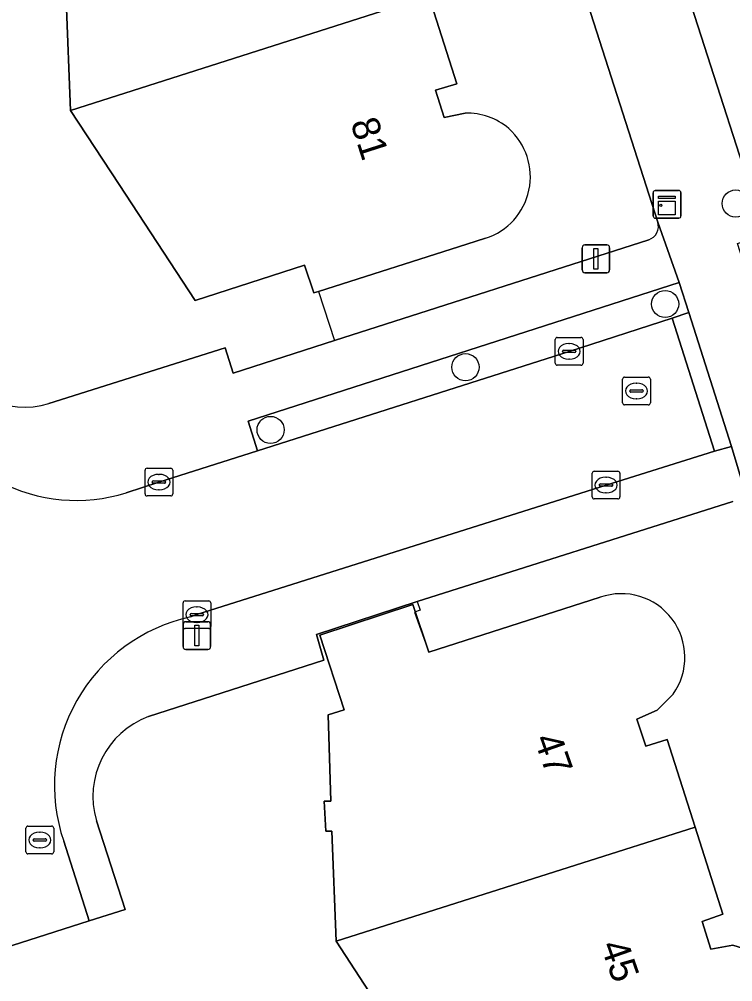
# Model space of a CAD drawing. Extents: x 159499 to 160349, y 382524 to 383273.
# Drawn here: x 159703.39 to 159729.11, y 382839.21 to 382873.89 of the extents above; entities that cross this region are included whole.
import ezdxf

# ---------------------------------------------------------------- set-up
doc = ezdxf.new("R2010")
doc.units = 0
for name, color, linetype in [('IMGEO_Boom', 7, 'Continuous'), ('IMGEO_Erf', 7, 'Continuous'), ('IMGEO_Groenvoorziening', 7, 'Continuous'), ('IMGEO_Kast', 7, 'Continuous'), ('IMGEO_Kolk', 7, 'Continuous'), ('IMGEO_Lichtmast', 7, 'Continuous'), ('IMGEO_Muur', 7, 'Continuous'), ('IMGEO_Pand', 7, 'Continuous'), ('IMGEO_Pand_nummerreeks', 7, 'Continuous'), ('IMGEO_Rijbaan_lokaal_open', 7, 'Continuous'), ('IMGEO_Rioolput', 7, 'Continuous'), ('IMGEO_Voetpad_open', 7, 'Continuous')]:
    doc.layers.add(name, color=color, linetype=linetype)

msp = doc.modelspace()

# ---------------------------------------------------------------- linework, layer by layer
at = {"layer": 'IMGEO_Boom'}
for centre in [(159729.218, 382867.25), (159726.676, 382863.629), (159719.477, 382861.354), (159712.452, 382859.093)]:
    msp.add_circle(centre, 0.489, dxfattribs=at)
at = {"layer": 'IMGEO_Erf'}
for points in [[(159726.407, 382866.582), (159705.82, 382930.705)], [(159716.052, 382878.641), (159716.38, 382877.657), (159717.146, 382877.885), (159718.157, 382874.729), (159719.171, 382871.564), (159718.394, 382871.332), (159718.71, 382870.347), (159719.467, 382870.509)], [(159720.203, 382865.998), (159719.528, 382865.788), (159714.185, 382864.083), (159714.015, 382864.029), (159713.674, 382865.027), (159709.737, 382863.757), (159706.992, 382867.936), (159705.241, 382870.601), (159704.925, 382878.587)], [(159704.459, 382860.04), (159710.809, 382862.055), (159711.101, 382861.14), (159714.761, 382862.313), (159726.084, 382865.943)], [(159706.174, 382845.013), (159707.207, 382841.819), (159705.912, 382841.405), (159664.868, 382828.266), (159663.864, 382831.383), (159666.542, 382832.265), (159661.739, 382847.267), (159659.033, 382846.414), (159658.047, 382849.524), (159699.119, 382862.705), (159700.405, 382863.118), (159700.812, 382861.848)], [(159729.113, 382856.514), (159717.74, 382852.909), (159714.109, 382851.726), (159714.375, 382850.795), (159708.057, 382848.765)], [(159714.223, 382851.698), (159717.585, 382852.806), (159718.151, 382851.09), (159724.337, 382853.063)], [(159734.475, 382821.398), (159728.286, 382819.442), (159728.827, 382818.014), (159725.74, 382817.391), (159725.188, 382819.543), (159724.024, 382819.172), (159719.547, 382825.96), (159719.219, 382833.928), (159714.816, 382840.671), (159714.658, 382844.641), (159714.438, 382844.631), (159714.386, 382845.722), (159714.626, 382845.723), (159714.532, 382848.826), (159715.109, 382849.012), (159714.223, 382851.698)], [(159726.963, 382849.575), (159726.392, 382848.995), (159725.65, 382848.673), (159725.979, 382847.696), (159726.751, 382847.942), (159727.759, 382844.784), (159728.761, 382841.646), (159728.006, 382841.381), (159728.326, 382840.39), (159729.119, 382840.528), (159729.847, 382840.303)]]:
    msp.add_lwpolyline(points, dxfattribs=at)
for centre, radius, start, end in [((159719.534, 382868.211), 2.299, 49.1866, 91.6585), ((159719.491, 382868.212), 2.326, 287.8266, 48.3742), ((159725.926, 382866.424), 0.506, 288.1944, 18.1745), ((159703.607, 382862.904), 2.988, 200.6996, 286.5606), ((159725.097, 382850.903), 2.29, 324.5583, 109.3915), ((159709.121, 382845.882), 3.073, 110.2611, 196.4379)]:
    msp.add_arc(centre, radius, start, end, dxfattribs=at)
at = {"layer": 'IMGEO_Groenvoorziening'}
msp.add_lwpolyline([(159711.979, 382858.343), (159723.216, 382861.922), (159726.932, 382863.118), (159727.53, 382863.325), (159727.182, 382864.402), (159711.648, 382859.405)], close=True, dxfattribs=at)
at = {"layer": 'IMGEO_Kast'}
for p, q in [((159726.243, 382866.796), (159726.243, 382867.637)), ((159726.243, 382867.637), (159726.243, 382866.796)), ((159726.318, 382867.721), (159727.159, 382867.721)), ((159727.159, 382867.721), (159726.318, 382867.721)), ((159727.243, 382867.646), (159727.243, 382866.805)), ((159727.243, 382866.805), (159727.243, 382867.646)), ((159727.168, 382866.721), (159726.327, 382866.721)), ((159726.327, 382866.721), (159727.168, 382866.721))]:
    msp.add_line(p, q, dxfattribs=at)
for points in [[(159726.438, 382867.511), (159727.038, 382867.511), (159727.038, 382867.426), (159726.438, 382867.426), (159726.438, 382867.511)], [(159726.438, 382867.336), (159727.038, 382867.336), (159727.038, 382866.847), (159726.438, 382866.847), (159726.438, 382867.336)]]:
    msp.add_lwpolyline(points, dxfattribs=at)
msp.add_circle((159726.522, 382867.185), 0.0377, dxfattribs=at)
for centre, start, end in [((159726.321, 382867.643), 92.4484, 184.2845), ((159726.321, 382867.643), 92.4484, 184.2845), ((159727.165, 382867.643), 2.4484, 94.2845), ((159727.165, 382867.643), 2.4484, 94.2845), ((159727.165, 382866.799), 272.4484, 4.2845), ((159727.165, 382866.799), 272.4484, 4.2845), ((159726.321, 382866.799), 182.4484, 274.2845), ((159726.321, 382866.799), 182.4484, 274.2845)]:
    msp.add_arc(centre, 0.0779, start, end, dxfattribs=at)
at = {"layer": 'IMGEO_Kolk'}
for p, q in [((159722.714, 382861.497), (159722.714, 382862.349)), ((159722.789, 382862.423), (159723.641, 382862.423)), ((159723.715, 382862.349), (159723.715, 382861.497)), ((159723.016, 382861.966), (159723.414, 382861.966)), ((159723.202, 382862.203), (159723.227, 382862.203)), ((159722.973, 382861.917), (159722.973, 382861.929)), ((159723.411, 382861.88), (159723.013, 382861.88)), ((159723.225, 382861.643), (159723.2, 382861.643)), ((159723.457, 382861.929), (159723.457, 382861.917)), ((159723.641, 382861.423), (159722.789, 382861.423)), ((159707.926, 382856.787), (159707.926, 382857.639)), ((159708.001, 382857.713), (159708.853, 382857.713)), ((159708.414, 382857.493), (159708.439, 382857.493)), ((159708.927, 382857.639), (159708.927, 382856.787)), ((159724.044, 382856.68), (159724.044, 382857.532)), ((159724.119, 382857.606), (159724.971, 382857.606)), ((159725.045, 382857.532), (159725.045, 382856.68)), ((159708.185, 382857.207), (159708.185, 382857.219)), ((159708.623, 382857.17), (159708.225, 382857.17)), ((159708.228, 382857.256), (159708.626, 382857.256)), ((159708.669, 382857.219), (159708.669, 382857.207)), ((159724.303, 382857.1), (159724.303, 382857.112)), ((159724.346, 382857.149), (159724.744, 382857.149)), ((159724.532, 382857.386), (159724.557, 382857.386)), ((159724.787, 382857.112), (159724.787, 382857.1)), ((159708.437, 382856.933), (159708.412, 382856.933)), ((159724.741, 382857.063), (159724.343, 382857.063)), ((159724.555, 382856.826), (159724.53, 382856.826)), ((159708.853, 382856.713), (159708.001, 382856.713)), ((159724.971, 382856.606), (159724.119, 382856.606)), ((159709.37, 382852.935), (159710.222, 382852.935)), ((159709.295, 382852.009), (159709.295, 382852.861)), ((159709.783, 382852.715), (159709.808, 382852.715)), ((159710.296, 382852.861), (159710.296, 382852.009)), ((159709.554, 382852.429), (159709.554, 382852.441)), ((159709.992, 382852.392), (159709.594, 382852.392)), ((159709.597, 382852.478), (159709.995, 382852.478)), ((159710.038, 382852.441), (159710.038, 382852.429)), ((159710.222, 382851.935), (159709.37, 382851.935)), ((159709.806, 382852.155), (159709.781, 382852.155))]:
    msp.add_line(p, q, dxfattribs=at)
for points in [[(159722.714, 382861.497), (159722.714, 382862.349)], [(159722.789, 382862.423), (159723.641, 382862.423)], [(159723.715, 382862.349), (159723.715, 382861.497)], [(159723.641, 382861.423), (159722.789, 382861.423)], [(159707.926, 382856.787), (159707.926, 382857.639)], [(159708.001, 382857.713), (159708.853, 382857.713)], [(159708.927, 382857.639), (159708.927, 382856.787)], [(159724.044, 382856.68), (159724.044, 382857.532)], [(159724.119, 382857.606), (159724.971, 382857.606)], [(159725.045, 382857.532), (159725.045, 382856.68)], [(159708.853, 382856.713), (159708.001, 382856.713)], [(159724.971, 382856.606), (159724.119, 382856.606)], [(159709.37, 382852.935), (159710.222, 382852.935)], [(159709.295, 382852.009), (159709.295, 382852.861)], [(159710.296, 382852.861), (159710.296, 382852.009)], [(159710.222, 382851.935), (159709.37, 382851.935)]]:
    msp.add_lwpolyline(points, dxfattribs=at)
for centre, radius, start, end in [((159722.791, 382862.347), 0.0765, 91.552, 178.448), ((159722.791, 382862.347), 0.0765, 91.552, 178.448), ((159723.639, 382862.347), 0.0765, 1.552, 88.448), ((159723.639, 382862.347), 0.0765, 1.552, 88.448), ((159723.013, 382861.926), 0.0403, 85.8775, 175.7526), ((159723.418, 382861.928), 0.0386, 1.7309, 96.639), ((159723.01, 382861.916), 0.0366, 178.938, 274.7102), ((159723.414, 382861.923), 0.043, 264.8664, 352.4533), ((159722.791, 382861.499), 0.0765, 181.552, 268.448), ((159722.791, 382861.499), 0.0765, 181.552, 268.448), ((159723.639, 382861.499), 0.0765, 271.552, 358.448), ((159723.639, 382861.499), 0.0765, 271.552, 358.448), ((159708.003, 382857.637), 0.0765, 91.552, 178.448), ((159708.003, 382857.637), 0.0765, 91.552, 178.448), ((159708.851, 382857.637), 0.0765, 1.552, 88.448), ((159708.851, 382857.637), 0.0765, 1.552, 88.448), ((159724.121, 382857.53), 0.0765, 91.552, 178.448), ((159724.121, 382857.53), 0.0765, 91.552, 178.448), ((159724.969, 382857.53), 0.0765, 1.552, 88.448), ((159724.969, 382857.53), 0.0765, 1.552, 88.448), ((159708.225, 382857.216), 0.0403, 85.8775, 175.7526), ((159708.222, 382857.206), 0.0366, 178.938, 274.7102), ((159708.626, 382857.213), 0.043, 264.8664, 352.4533), ((159708.63, 382857.218), 0.0386, 1.7309, 96.639), ((159724.343, 382857.109), 0.0403, 85.8775, 175.7526), ((159724.34, 382857.099), 0.0366, 178.938, 274.7102), ((159724.744, 382857.106), 0.043, 264.8664, 352.4533), ((159724.748, 382857.111), 0.0386, 1.7309, 96.639), ((159708.003, 382856.789), 0.0765, 181.552, 268.448), ((159708.003, 382856.789), 0.0765, 181.552, 268.448), ((159708.851, 382856.789), 0.0765, 271.552, 358.448), ((159708.851, 382856.789), 0.0765, 271.552, 358.448), ((159724.121, 382856.682), 0.0765, 181.552, 268.448), ((159724.121, 382856.682), 0.0765, 181.552, 268.448), ((159724.969, 382856.682), 0.0765, 271.552, 358.448), ((159724.969, 382856.682), 0.0765, 271.552, 358.448), ((159709.372, 382852.859), 0.0765, 91.552, 178.448), ((159709.372, 382852.859), 0.0765, 91.552, 178.448), ((159710.22, 382852.859), 0.0765, 1.552, 88.448), ((159710.22, 382852.859), 0.0765, 1.552, 88.448), ((159709.594, 382852.438), 0.0403, 85.8775, 175.7526), ((159709.591, 382852.428), 0.0366, 178.938, 274.7102), ((159709.995, 382852.435), 0.043, 264.8664, 352.4533), ((159709.999, 382852.44), 0.0386, 1.7309, 96.639), ((159709.372, 382852.011), 0.0765, 181.552, 268.448), ((159709.372, 382852.011), 0.0765, 181.552, 268.448), ((159710.22, 382852.011), 0.0765, 271.552, 358.448), ((159710.22, 382852.011), 0.0765, 271.552, 358.448)]:
    msp.add_arc(centre, radius, start, end, dxfattribs=at)
for centre, major_axis, ratio, start_param, end_param in [((159723.201, 382861.923), (-0.387, 0.002), 0.722429, 4.712389, 7.853982), ((159723.226, 382861.923), (-0.39, 0.002), 0.717154, 1.570796, 4.712389), ((159708.413, 382857.213), (-0.387, 0.002), 0.722429, 4.712389, 7.853982), ((159708.438, 382857.213), (-0.39, 0.002), 0.717154, 1.570796, 4.712389), ((159724.531, 382857.106), (-0.387, 0.002), 0.722429, 4.712389, 7.853982), ((159724.556, 382857.106), (-0.39, 0.002), 0.717154, 1.570796, 4.712389), ((159709.782, 382852.435), (-0.387, 0.002), 0.722429, 4.712389, 7.853982), ((159709.807, 382852.435), (-0.39, 0.002), 0.717154, 1.570796, 4.712389)]:
    msp.add_ellipse(centre, major_axis=major_axis, ratio=ratio, start_param=start_param, end_param=end_param, dxfattribs=at)
at = {"layer": 'IMGEO_Lichtmast'}
for p, q in [((159723.684, 382864.859), (159723.684, 382865.659)), ((159723.684, 382865.659), (159723.684, 382864.859)), ((159723.784, 382865.759), (159724.574, 382865.759)), ((159724.574, 382865.759), (159723.784, 382865.759)), ((159724.674, 382865.659), (159724.674, 382864.859)), ((159724.674, 382864.859), (159724.674, 382865.659)), ((159724.574, 382864.759), (159723.784, 382864.759)), ((159723.784, 382864.759), (159724.574, 382864.759)), ((159709.298, 382851.284), (159709.298, 382852.084)), ((159709.298, 382852.084), (159709.298, 382851.284)), ((159709.398, 382852.184), (159710.188, 382852.184)), ((159710.188, 382852.184), (159709.398, 382852.184)), ((159710.288, 382852.084), (159710.288, 382851.284)), ((159710.288, 382851.284), (159710.288, 382852.084)), ((159710.188, 382851.184), (159709.398, 382851.184)), ((159709.398, 382851.184), (159710.188, 382851.184))]:
    msp.add_line(p, q, dxfattribs=at)
for points in [[(159724.104, 382865.634), (159724.254, 382865.634), (159724.254, 382864.884), (159724.104, 382864.884), (159724.104, 382865.634)], [(159709.718, 382852.059), (159709.868, 382852.059), (159709.868, 382851.309), (159709.718, 382851.309), (159709.718, 382852.059)]]:
    msp.add_lwpolyline(points, dxfattribs=at)
for centre, start, end in [((159723.784, 382865.659), 90, 180), ((159723.784, 382865.659), 90, 180), ((159724.574, 382865.659), 0, 90), ((159724.574, 382865.659), 360, 90), ((159723.784, 382864.859), 180, 270), ((159723.784, 382864.859), 180, 270), ((159724.574, 382864.859), 270, 0), ((159724.574, 382864.859), 270, 0), ((159709.398, 382852.084), 90, 180), ((159709.398, 382852.084), 90, 180), ((159710.188, 382852.084), 0, 90), ((159710.188, 382852.084), 360, 90), ((159709.398, 382851.284), 180, 270), ((159709.398, 382851.284), 180, 270), ((159710.188, 382851.284), 270, 0), ((159710.188, 382851.284), 270, 0)]:
    msp.add_arc(centre, 0.1, start, end, dxfattribs=at)
at = {"layer": 'IMGEO_Muur'}
for points in [[(159714.185, 382864.083), (159714.761, 382862.313)], [(159714.761, 382862.313), (159711.101, 382861.14), (159710.809, 382862.055), (159704.459, 382860.04)], [(159708.057, 382848.765), (159714.375, 382850.795), (159714.109, 382851.726), (159717.74, 382852.909)], [(159717.74, 382852.909), (159717.841, 382852.604), (159717.635, 382852.523), (159718.151, 382851.09)], [(159706.174, 382845.013), (159707.207, 382841.819)]]:
    msp.add_lwpolyline(points, dxfattribs=at)
for centre, radius, start, end in [((159703.607, 382862.904), 2.988, 200.6996, 286.5606), ((159709.121, 382845.882), 3.073, 110.2611, 196.4379)]:
    msp.add_arc(centre, radius, start, end, dxfattribs=at)
at = {"layer": 'IMGEO_Pand'}
for points in [[(159717.354, 382882.542), (159704.925, 382878.587), (159705.241, 382870.601), (159718.157, 382874.729), (159717.146, 382877.885), (159716.38, 382877.657), (159716.052, 382878.641)], [(159719.467, 382870.509), (159718.71, 382870.347), (159718.394, 382871.332), (159719.171, 382871.564), (159718.157, 382874.729), (159705.241, 382870.601), (159706.992, 382867.936), (159709.737, 382863.757), (159713.674, 382865.027), (159714.015, 382864.029), (159714.185, 382864.083), (159719.528, 382865.788), (159720.203, 382865.998)], [(159724.337, 382853.063), (159718.151, 382851.09), (159717.585, 382852.806), (159714.223, 382851.698), (159715.109, 382849.012), (159714.532, 382848.826), (159714.626, 382845.723), (159714.386, 382845.722), (159714.438, 382844.631), (159714.658, 382844.641), (159714.816, 382840.671), (159727.759, 382844.784), (159726.751, 382847.942)], [(159726.751, 382847.942), (159725.979, 382847.696), (159725.65, 382848.673), (159726.392, 382848.995), (159726.963, 382849.575)], [(159729.847, 382840.303), (159729.119, 382840.528), (159728.326, 382840.39), (159728.006, 382841.381), (159728.761, 382841.646), (159727.759, 382844.784), (159714.816, 382840.671), (159719.219, 382833.928), (159731.651, 382837.94)]]:
    msp.add_lwpolyline(points, dxfattribs=at)
for centre, radius, start, end in [((159719.534, 382868.211), 2.299, 49.1866, 91.6585), ((159719.491, 382868.212), 2.326, 287.8266, 48.3742), ((159725.097, 382850.903), 2.29, 324.5583, 109.3915)]:
    msp.add_arc(centre, radius, start, end, dxfattribs=at)
at = {"layer": 'IMGEO_Rijbaan_lokaal_open'}
msp.add_lwpolyline([(159737.432, 382843.824), (159744.243, 382846.026), (159744.191, 382846.188), (159737.539, 382866.925), (159727.07, 382899.511), (159726.994, 382899.746), (159720.253, 382897.428), (159720.284, 382897.331), (159721.097, 382894.788), (159722.888, 382889.098), (159725.791, 382880.115), (159727.623, 382874.357), (159730.279, 382866.12), (159733.33, 382856.538), (159733.407, 382856.312), (159735.46, 382849.969), (159737.305, 382844.219)], close=True, dxfattribs=at)
for points in [[(159709.567, 382852.354), (159709.795, 382852.437), (159724.544, 382857.107), (159728.46, 382858.329), (159726.932, 382863.118), (159723.216, 382861.922), (159711.979, 382858.343), (159708.428, 382857.212), (159707.25, 382856.83)], [(159699.712, 382860.799), (159699.119, 382862.705), (159658.047, 382849.524), (159659.033, 382846.414), (159661.739, 382847.267), (159666.542, 382832.265), (159663.864, 382831.383), (159664.868, 382828.266), (159705.912, 382841.405), (159704.996, 382844.273)]]:
    msp.add_lwpolyline(points, dxfattribs=at)
for centre, radius, start, end in [((159705.451, 382862.556), 6.002, 197.02, 287.4435), ((159710.87, 382846.283), 6.209, 102.1186, 198.8922)]:
    msp.add_arc(centre, radius, start, end, dxfattribs=at)
at = {"layer": 'IMGEO_Rioolput'}
for p, q in [((159725.141, 382860.069), (159725.141, 382860.921)), ((159725.216, 382860.995), (159726.068, 382860.995)), ((159726.142, 382860.921), (159726.142, 382860.069)), ((159725.629, 382860.775), (159725.654, 382860.775)), ((159725.4, 382860.489), (159725.4, 382860.501)), ((159725.838, 382860.452), (159725.44, 382860.452)), ((159725.443, 382860.538), (159725.841, 382860.538)), ((159725.652, 382860.215), (159725.627, 382860.215)), ((159725.884, 382860.501), (159725.884, 382860.489)), ((159726.068, 382859.995), (159725.216, 382859.995)), ((159703.632, 382843.892), (159703.632, 382844.744)), ((159703.707, 382844.818), (159704.559, 382844.818)), ((159704.633, 382844.744), (159704.633, 382843.892)), ((159703.891, 382844.312), (159703.891, 382844.324)), ((159704.329, 382844.275), (159703.931, 382844.275)), ((159703.934, 382844.361), (159704.332, 382844.361)), ((159704.12, 382844.598), (159704.145, 382844.598)), ((159704.375, 382844.324), (159704.375, 382844.312)), ((159704.143, 382844.038), (159704.118, 382844.038)), ((159704.559, 382843.818), (159703.707, 382843.818))]:
    msp.add_line(p, q, dxfattribs=at)
for points in [[(159725.141, 382860.069), (159725.141, 382860.921)], [(159725.216, 382860.995), (159726.068, 382860.995)], [(159726.142, 382860.921), (159726.142, 382860.069)], [(159726.068, 382859.995), (159725.216, 382859.995)], [(159703.632, 382843.892), (159703.632, 382844.744)], [(159703.707, 382844.818), (159704.559, 382844.818)], [(159704.633, 382844.744), (159704.633, 382843.892)], [(159704.559, 382843.818), (159703.707, 382843.818)]]:
    msp.add_lwpolyline(points, dxfattribs=at)
for centre, radius, start, end in [((159725.218, 382860.919), 0.0765, 91.552, 178.448), ((159725.218, 382860.919), 0.0765, 91.552, 178.448), ((159726.066, 382860.919), 0.0765, 1.552, 88.448), ((159726.066, 382860.919), 0.0765, 1.552, 88.448), ((159725.44, 382860.498), 0.0403, 85.8775, 175.7526), ((159725.437, 382860.488), 0.0366, 178.938, 274.7102), ((159725.841, 382860.495), 0.043, 264.8664, 352.4533), ((159725.845, 382860.5), 0.0386, 1.7309, 96.639), ((159725.218, 382860.071), 0.0765, 181.552, 268.448), ((159725.218, 382860.071), 0.0765, 181.552, 268.448), ((159726.066, 382860.071), 0.0765, 271.552, 358.448), ((159726.066, 382860.071), 0.0765, 271.552, 358.448), ((159703.709, 382844.742), 0.0765, 91.552, 178.448), ((159703.709, 382844.742), 0.0765, 91.552, 178.448), ((159704.557, 382844.742), 0.0765, 1.552, 88.448), ((159704.557, 382844.742), 0.0765, 1.552, 88.448), ((159703.931, 382844.321), 0.0403, 85.8775, 175.7526), ((159703.928, 382844.311), 0.0366, 178.938, 274.7102), ((159704.332, 382844.318), 0.043, 264.8664, 352.4533), ((159704.336, 382844.323), 0.0386, 1.7309, 96.639), ((159703.709, 382843.894), 0.0765, 181.552, 268.448), ((159703.709, 382843.894), 0.0765, 181.552, 268.448), ((159704.557, 382843.894), 0.0765, 271.552, 358.448), ((159704.557, 382843.894), 0.0765, 271.552, 358.448)]:
    msp.add_arc(centre, radius, start, end, dxfattribs=at)
for centre, major_axis, ratio, start_param, end_param in [((159725.628, 382860.495), (-0.387, 0.002), 0.722429, 4.712389, 7.853982), ((159725.653, 382860.495), (-0.39, 0.002), 0.717154, 1.570796, 4.712389), ((159704.119, 382844.318), (-0.387, 0.002), 0.722429, 4.712389, 7.853982), ((159704.144, 382844.318), (-0.39, 0.002), 0.717154, 1.570796, 4.712389)]:
    msp.add_ellipse(centre, major_axis=major_axis, ratio=ratio, start_param=start_param, end_param=end_param, dxfattribs=at)
at = {"layer": 'IMGEO_Voetpad_open'}
for points in [[(159705.82, 382930.705), (159726.407, 382866.582), (159727.182, 382864.402), (159727.53, 382863.325), (159729.07, 382858.5), (159729.755, 382856.197), (159740.727, 382822.055), (159740.732, 382822.044), (159741.322, 382820.139), (159742.845, 382815.409), (159744.764, 382809.45), (159747.728, 382800.527), (159763.767, 382750)], [(159741.978, 382829.581), (159741.573, 382829.435), (159739.751, 382835.181), (159740.162, 382835.315), (159738.87, 382839.341), (159737.432, 382843.824), (159737.305, 382844.219), (159736.886, 382844.1), (159735.018, 382849.822), (159735.46, 382849.969), (159733.407, 382856.312), (159733.33, 382856.538), (159732.339, 382856.222), (159729.288, 382865.804), (159730.279, 382866.12), (159727.623, 382874.357)], [(159727.182, 382864.402), (159726.407, 382866.582)], [(159726.084, 382865.943), (159714.761, 382862.313), (159711.101, 382861.14), (159710.809, 382862.055), (159704.459, 382860.04)], [(159707.25, 382856.83), (159708.428, 382857.212), (159711.979, 382858.343), (159711.648, 382859.405), (159727.182, 382864.402)], [(159729.755, 382856.197), (159729.07, 382858.5), (159728.46, 382858.329), (159724.544, 382857.107), (159709.795, 382852.437), (159709.567, 382852.354)], [(159714.375, 382850.795), (159714.109, 382851.726), (159717.74, 382852.909), (159729.113, 382856.514)], [(159708.057, 382848.765), (159714.375, 382850.795)], [(159704.996, 382844.273), (159705.912, 382841.405), (159707.207, 382841.819), (159706.174, 382845.013)]]:
    msp.add_lwpolyline(points, dxfattribs=at)
msp.add_lwpolyline([(159726.932, 382863.118), (159728.46, 382858.329), (159729.07, 382858.5), (159727.53, 382863.325)], close=True, dxfattribs=at)
for centre, radius, start, end in [((159725.926, 382866.424), 0.506, 288.1944, 18.1745), ((159703.607, 382862.904), 2.988, 200.6996, 286.5606), ((159705.451, 382862.556), 6.002, 197.02, 287.4435), ((159710.87, 382846.283), 6.209, 102.1186, 198.8922), ((159709.121, 382845.882), 3.073, 110.2611, 196.4379)]:
    msp.add_arc(centre, radius, start, end, dxfattribs=at)

# ---------------------------------------------------------------- texts
at = {"layer": 'IMGEO_Pand_nummerreeks'}
for s, rotation, p in [('81', 287.7795, (159715.324, 382870.162)), ('47', 289.2741, (159721.937, 382847.964)), ('45', 289.2723, (159724.336, 382840.519))]:
    msp.add_text(s, height=1, rotation=rotation, dxfattribs=at).set_placement(p)

doc.saveas('drawing.dxf')
